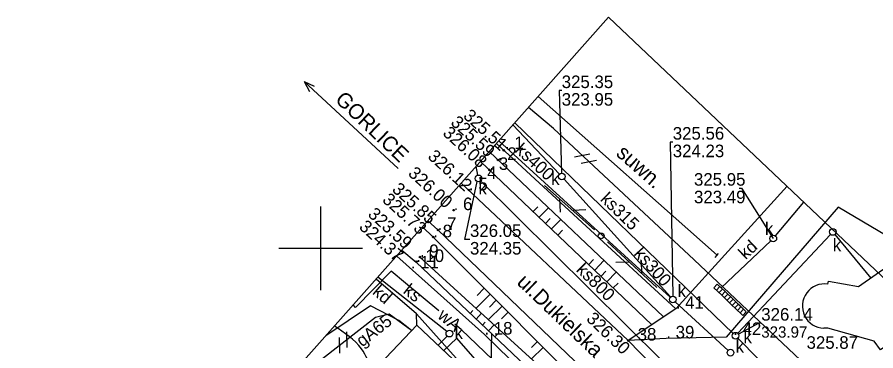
# Model space of a CAD drawing. Extents: x 4632591 to 4653165, y 5351032 to 5369868.
# Drawn here: x 4644663.8 to 4644766.2, y 5358587.8 to 5358627.6 of the extents above; entities that cross this region are included whole.
import ezdxf

# ---------------------------------------------------------------- set-up
doc = ezdxf.new("R2010")
doc.units = 0
for name, color, linetype in [('EADPD_238', 7, 'Continuous'), ('EBUPP_312', 7, 'Continuous'), ('EDZPX_299', 7, 'Continuous'), ('SDRPK_420', 7, 'Continuous'), ('SDRPK_423', 7, 'Continuous'), ('SDRPK_432', 7, 'Continuous'), ('SZOPO_902', 7, 'Continuous'), ('SZOPO_903', 7, 'Continuous'), ('UEEPA_510', 7, 'Continuous'), ('UGGPO_553', 7, 'Continuous'), ('UKKPA_506', 7, 'Continuous'), ('UKKPA_509', 7, 'Continuous'), ('UKKPB_562', 7, 'Continuous'), ('UTTTA_521', 7, 'Continuous'), ('UWWPO_581', 7, 'Continuous'), ('Warstwa 40', 7, 'Continuous'), ('Warstwa 60', 7, 'Continuous'), ('Warstwa 62', 7, 'Continuous'), ('WUKPS_403', 7, 'Continuous'), ('WUKPS_820', 7, 'Continuous'), ('WUKPS_823', 7, 'Continuous'), ('WUKPS_824', 7, 'Continuous'), ('WWRPH_811', 7, 'Continuous')]:
    doc.layers.add(name, color=color, linetype=linetype)

msp = doc.modelspace()

# ---------------------------------------------------------------- linework, layer by layer
at = {"layer": 'EBUPP_312'}
for p, q in [((4644747.26, 5358599.16), (4644725.93, 5358618.12)), ((4644747.05, 5358598.91), (4644747.43, 5358599.36)), ((4644705.01, 5358584.02), (4644711.46, 5358590.84)), ((4644711.46, 5358590.84), (4644718.85, 5358583.85)), ((4644760.46, 5358590.46), (4644759.99, 5358590.46))]:
    msp.add_line(p, q, dxfattribs=at)
for points in [[(4644760.47, 5358595.72), (4644760.54, 5358596.09), (4644764.13, 5358595.43), (4644775.98, 5358603.7), (4644780.37, 5358597.41), (4644775.58, 5358594.07)], [(4644771.51, 5358581.18), (4644771.79, 5358585.56), (4644769.05, 5358589.47), (4644766.74, 5358587.89), (4644765.98, 5358588.9), (4644760.46, 5358590.46)]]:
    msp.add_lwpolyline(points, dxfattribs=at)
msp.add_arc((4644760.08, 5358593.1), 2.65, 81.3979, 268.009, dxfattribs=at)
at = {"layer": 'EDZPX_299'}
for p, q in [((4644730.26, 5358610.92), (4644732.09, 5358611.26)), ((4644731.06, 5358610.17), (4644732.89, 5358610.51)), ((4644703.16, 5358588.16), (4644703.1, 5358590.02)), ((4644702.29, 5358587.48), (4644702.23, 5358589.34))]:
    msp.add_line(p, q, dxfattribs=at)
at = {"layer": 'SDRPK_420'}
msp.add_line((4644742.34, 5358592.78), (4644736.68, 5358588.98), dxfattribs=at)
for points in [[(4644716.77, 5358607.78), (4644736.68, 5358588.98), (4644743.87, 5358581.58), (4644750.16, 5358575.12), (4644760.49, 5358564.21), (4644766.47, 5358558.47), (4644774.19, 5358550.53), (4644786.69, 5358537.74), (4644789.51, 5358534.89)], [(4644712.76, 5358603.26), (4644713.95, 5358602.19), (4644735.11, 5358581.89), (4644746.11, 5358570.7), (4644757.33, 5358559.27), (4644771.55, 5358544.69), (4644780.39, 5358535.5), (4644785.1, 5358530.72)]]:
    msp.add_lwpolyline(points, dxfattribs=at)
at = {"layer": 'SDRPK_423'}
msp.add_line((4644741.21, 5358589.24), (4644736.68, 5358588.98), dxfattribs=at)
msp.add_lwpolyline([(4644770.35, 5358599.76), (4644761.7, 5358604.91), (4644748.36, 5358589.39), (4644741.21, 5358589.24)], dxfattribs=at)
at = {"layer": 'SDRPK_432'}
msp.add_line((4644698.03, 5358619.91), (4644698.67, 5358618.73), dxfattribs=at)
msp.add_lwpolyline([(4644709.25, 5358609.51), (4644698.03, 5358619.91), (4644699.24, 5358619.33)], dxfattribs=at)
at = {"layer": 'SZOPO_902'}
msp.add_lwpolyline([(4644720.96, 5358612.51), (4644742.34, 5358592.78), (4644755.61, 5358607.4)], dxfattribs=at)
at = {"layer": 'SZOPO_903'}
msp.add_lwpolyline([(4644709.09, 5358599.07), (4644719.52, 5358589.7), (4644731.52, 5358578)], dxfattribs=at)
at = {"layer": 'UEEPA_510'}
msp.add_circle((4644733.44, 5358601.48), 0.35, dxfattribs=at)
at = {"layer": 'UGGPO_553'}
for points in [[(4644783.41, 5358581.03), (4644773.38, 5358571.35), (4644744.52, 5358598.63), (4644727.75, 5358614.29), (4644724.77, 5358616.81)], [(4644710.84, 5358590.18), (4644709.32, 5358591.39), (4644705.94, 5358593.14), (4644700.61, 5358589.55)], [(4644710.84, 5358590.18), (4644708.18, 5358592.13), (4644706.52, 5358591.75), (4644693.55, 5358581.58)]]:
    msp.add_lwpolyline(points, dxfattribs=at)
at = {"layer": 'UKKPA_506'}
for points in [[(4644728.74, 5358618.82), (4644728.44, 5358618.82), (4644728.73, 5358608.96)], [(4644741.98, 5358612.67), (4644741.68, 5358612.67), (4644741.97, 5358594.29)], [(4644717.8, 5358601.04), (4644717.2, 5358601.06), (4644718.67, 5358607.96)], [(4644749.89, 5358607.17), (4644750.19, 5358607.17), (4644753.96, 5358601.16)], [(4644752.53, 5358591.06), (4644752.23, 5358591.06), (4644749.81, 5358589.75)]]:
    msp.add_lwpolyline(points, dxfattribs=at)
for centre in [(4644728.76, 5358608.56), (4644718.81, 5358608.34), (4644761.06, 5358601.95), (4644753.96, 5358601.16), (4644741.98, 5358593.89), (4644715.35, 5358589.81), (4644749.46, 5358589.56), (4644748.87, 5358587.54)]:
    msp.add_circle(centre, 0.4, dxfattribs=at)
at = {"layer": 'UKKPA_509'}
for p, q in [((4644747.6, 5358595.43), (4644747.18, 5358594.99)), ((4644747.49, 5358594.69), (4644747.92, 5358595.13)), ((4644748.54, 5358594.52), (4644748.12, 5358594.09)), ((4644748.44, 5358593.78), (4644748.86, 5358594.22)), ((4644749.49, 5358593.62), (4644749.06, 5358593.18)), ((4644749.38, 5358592.88), (4644749.8, 5358593.32)), ((4644750.11, 5358593.02), (4644749.69, 5358592.58)), ((4644750.01, 5358592.28), (4644750.43, 5358592.72))]:
    msp.add_line(p, q, dxfattribs=at)
for points in [[(4644747.29, 5358595.73), (4644748.23, 5358594.83), (4644747.81, 5358594.39), (4644746.87, 5358595.29)], [(4644748.23, 5358594.83), (4644749.17, 5358593.92), (4644748.75, 5358593.48), (4644747.81, 5358594.39)], [(4644749.17, 5358593.92), (4644750.11, 5358593.02), (4644749.69, 5358592.58), (4644748.75, 5358593.48)], [(4644749.8, 5358593.32), (4644750.74, 5358592.42), (4644750.32, 5358591.98), (4644749.38, 5358592.88)]]:
    msp.add_lwpolyline(points, close=True, dxfattribs=at)
at = {"layer": 'UKKPB_562'}
for p, q in [((4644728.48, 5358608.85), (4644722.93, 5358614.73)), ((4644749.17, 5358589.84), (4644723.15, 5358614.98)), ((4644741.68, 5358594.16), (4644721.25, 5358612.84)), ((4644718.74, 5358608.73), (4644718.55, 5358609.79)), ((4644741.71, 5358594.19), (4644729.03, 5358608.26)), ((4644754.22, 5358601.47), (4644757.59, 5358605.52)), ((4644747.75, 5358595.29), (4644753.67, 5358600.89)), ((4644760.79, 5358601.66), (4644749.73, 5358589.85)), ((4644761.31, 5358601.64), (4644765.59, 5358596.45)), ((4644748.58, 5358587.81), (4644742.27, 5358593.62)), ((4644711.46, 5358590.84), (4644711.44, 5358592.16))]:
    msp.add_line(p, q, dxfattribs=at)
for points in [[(4644719.07, 5358608.03), (4644749.38, 5358577.96)], [(4644718.85, 5358583.85), (4644711.44, 5358592.16), (4644706.62, 5358596.32)], [(4644715.04, 5358590.06), (4644706.81, 5358596.54)], [(4644714.01, 5358588.42), (4644715.07, 5358589.52)], [(4644749.74, 5358589.28), (4644771.59, 5358567.02)]]:
    msp.add_lwpolyline(points, dxfattribs=at)
at = {"layer": 'UTTTA_521'}
for p, q in [((4644732.66, 5358602.18), (4644726.68, 5358607.5)), ((4644728.47, 5358605.9), (4644728.57, 5358604.3)), ((4644730.02, 5358604.53), (4644731.61, 5358604.62)), ((4644734.21, 5358600.77), (4644740.06, 5358595.31)), ((4644736.79, 5358598.36), (4644735.19, 5358598.3)), ((4644738.31, 5358596.95), (4644738.25, 5358598.55))]:
    msp.add_line(p, q, dxfattribs=at)
at = {"layer": 'UWWPO_581'}
for points in [[(4644714.1, 5358592.52), (4644710.12, 5358595.82), (4644708.4, 5358597.25), (4644704.15, 5358592.94), (4644703.87, 5358593.23)], [(4644734.99, 5358571.06), (4644724.04, 5358580.83), (4644721.45, 5358585.79), (4644716.76, 5358590.31), (4644715.99, 5358590.95)], [(4644722.06, 5358580.45), (4644720.03, 5358584.88), (4644716.23, 5358589.27), (4644714.67, 5358587.81)]]:
    msp.add_lwpolyline(points, dxfattribs=at)
at = {"layer": 'Warstwa 40'}
msp.add_lwpolyline([(4644810.83, 5358555.03), (4644734.32, 5358627.59), (4644688.9, 5358576.34), (4644696.21, 5358541.05), (4644665.65, 5358513.08), (4644675.21, 5358482.87), (4644634.26, 5358446.15), (4644624.66, 5358448.08), (4644610.34, 5358444.41), (4644593.08, 5358445.77), (4644584.82, 5358446.42), (4644558.95, 5358331.35), (4644690.29, 5358293.2), (4644705.73, 5358386.52), (4644692.29, 5358404.57), (4644776.59, 5358522.67)], close=True, dxfattribs=at)
at = {"layer": 'Warstwa 60'}
for p, q in [((4644700, 5358595), (4644700, 5358605)), ((4644695, 5358600), (4644705, 5358600))]:
    msp.add_line(p, q, dxfattribs=at)
at = {"layer": 'WUKPS_403'}
for centre in [(4644721.83, 5358611.69), (4644721.14, 5358610.54), (4644720.12, 5358609.36), (4644717.7, 5358606.95), (4644715.86, 5358604.55), (4644714, 5358602.17), (4644713.43, 5358601.34), (4644711.84, 5358598.95), (4644711.39, 5358598.4), (4644736.68, 5358588.98)]:
    msp.add_circle(centre, 0.09, dxfattribs=at)
at = {"layer": 'WUKPS_820'}
for p, q in [((4644725.35, 5358604.37), (4644725.9, 5358604.94)), ((4644726.06, 5358603.7), (4644727.15, 5358604.84)), ((4644726.81, 5358602.97), (4644727.36, 5358603.55)), ((4644727.52, 5358602.3), (4644728.62, 5358603.45)), ((4644728.28, 5358601.58), (4644728.83, 5358602.15)), ((4644731.96, 5358598.06), (4644732.52, 5358598.64)), ((4644732.67, 5358597.39), (4644733.78, 5358598.55)), ((4644733.43, 5358596.66), (4644733.98, 5358597.25)), ((4644734.13, 5358595.99), (4644735.24, 5358597.16)), ((4644734.89, 5358595.27), (4644735.45, 5358595.85)), ((4644719.51, 5358595.22), (4644718.65, 5358594.37)), ((4644720.19, 5358594.53), (4644718.52, 5358592.86)), ((4644720.93, 5358593.79), (4644720.11, 5358592.97)), ((4644717.83, 5358592.22), (4644718.15, 5358592.56)), ((4644721.62, 5358593.1), (4644720.01, 5358591.49)), ((4644718.54, 5358591.55), (4644719.19, 5358592.24)), ((4644722.36, 5358592.36), (4644721.57, 5358591.57)), ((4644719.3, 5358590.83), (4644719.63, 5358591.18)), ((4644720.01, 5358590.16), (4644720.68, 5358590.87)), ((4644720.77, 5358589.44), (4644721.11, 5358589.8)), ((4644725.85, 5358588.86), (4644725.14, 5358588.16)), ((4644726.53, 5358588.17), (4644725.15, 5358586.79))]:
    msp.add_line(p, q, dxfattribs=at)
at = {"layer": 'WUKPS_823'}
msp.add_line((4644719.06, 5358610.37), (4644739.5, 5358590.87), dxfattribs=at)
for points in [[(4644712.13, 5358602.55), (4644713.43, 5358601.31), (4644734.25, 5358580.44)], [(4644709.66, 5358599.76), (4644711.37, 5358598.36), (4644732.07, 5358578.71)]]:
    msp.add_lwpolyline(points, dxfattribs=at)
at = {"layer": 'WUKPS_824'}
for p, q in [((4644720.1, 5358611.53), (4644740.89, 5358591.81)), ((4644711.84, 5358598.95), (4644732.98, 5358579.64))]:
    msp.add_line(p, q, dxfattribs=at)
at = {"layer": 'WWRPH_811'}
for points in [[(4644706.2, 5358585.27), (4644704.86, 5358588.01), (4644701.64, 5358590.71)], [(4644719.35, 5358579.58), (4644720.36, 5358583.57), (4644720.36, 5358587.15), (4644720.42, 5358589.77)]]:
    msp.add_spline(points, degree=3, dxfattribs=at)

# ---------------------------------------------------------------- texts
at = {"layer": 'EADPD_238'}
msp.add_text('suwn.', height=1.8, rotation=318.3714, dxfattribs=at).set_placement((4644735.11, 5358611.17))
at = {"layer": 'SDRPK_432'}
for s, p in [('GORLICE', (4644701.61, 5358617.62)), ('ul.Dukielska', (4644723.28, 5358595.82))]:
    msp.add_text(s, height=1.8, rotation=316.1883, dxfattribs=at).set_placement(p)
at = {"layer": 'UGGPO_553'}
msp.add_text('gA65', height=1.5, rotation=38.0978, dxfattribs=at).set_placement((4644704.96, 5358588.15))
at = {"layer": 'UKKPA_506'}
for s, height, p in [('325.35', 1.5, (4644728.74, 5358619.12)), ('323.95', 1.5, (4644728.74, 5358617.02)), ('325.56', 1.5, (4644741.98, 5358612.97)), ('324.23', 1.5, (4644741.98, 5358610.87)), ('k', 1.5, (4644727.47, 5358607.57)), ('325.95', 1.5, (4644744.51, 5358607.47)), ('k', 1.5, (4644718.81, 5358606.43)), ('323.49', 1.5, (4644744.51, 5358605.37)), ('326.05', 1.5, (4644717.8, 5358601.35)), ('k', 1.5, (4644752.97, 5358601.59)), ('324.35', 1.5, (4644717.8, 5358599.25)), ('k', 1.5, (4644761.06, 5358599.65)), ('k', 1.5, (4644742.55, 5358594.17)), ('326.14', 1.5, (4644752.53, 5358591.36)), ('k', 1.5, (4644715.97, 5358589.15)), ('323.97', 1.344, (4644752.53, 5358589.33)), ('k', 1.5, (4644750.41, 5358588.67)), ('325.87', 1.5, (4644757.93, 5358588)), ('k', 1.5, (4644749.47, 5358587.54))]:
    msp.add_text(s, height=height, dxfattribs=at).set_placement(p)
at = {"layer": 'UKKPB_562'}
for s, rotation, p in [('ks400', 317.5799, (4644723.06, 5358611.58)), ('ks315', 315.9764, (4644733.25, 5358605.75)), ('kd', 43.3947, (4644750.67, 5358598.57)), ('ks300', 312.034, (4644737.25, 5358599.29)), ('ks800', 315.2195, (4644730.38, 5358597.34)), ('kd', 319.2256, (4644706.07, 5358594.62)), ('ks', 321.7642, (4644709.73, 5358594.72))]:
    msp.add_text(s, height=1.5, rotation=rotation, dxfattribs=at).set_placement(p)
at = {"layer": 'UWWPO_581'}
msp.add_text('wA', height=1.5, rotation=320.326, dxfattribs=at).set_placement((4644713.84, 5358591.76))
at = {"layer": 'Warstwa 62'}
for s, p in [('. 1', (4644721.98, 5358611.84)), ('. 2', (4644721.13, 5358610.55)), ('. 3', (4644720.13, 5358609.35)), ('. 4', (4644718.74, 5358608.27)), ('. 5', (4644717.68, 5358606.92)), ('. 6', (4644715.86, 5358604.55)), ('. 8', (4644713.43, 5358601.31)), ('. 7', (4644713.95, 5358602.19)), ('. 10', (4644711.37, 5358598.36)), ('. 9', (4644711.84, 5358598.95)), ('. 11', (4644710.74, 5358597.59)), ('. 41', (4644742.34, 5358592.78)), ('. 18', (4644719.52, 5358589.7)), ('. 38', (4644736.68, 5358588.98)), ('. 39', (4644741.21, 5358589.24)), ('. 42', (4644749.19, 5358589.65))]:
    msp.add_text(s, height=1.5, dxfattribs=at).set_placement(p)
at = {"layer": 'WUKPS_403'}
for s, rotation, p in [('325.51', 317.5935, (4644716.9, 5358615.66)), ('325.59', 317.5935, (4644715.4, 5358614.87)), ('326.08', 317.5935, (4644714.45, 5358613.61)), ('326.12', 317.5935, (4644712.67, 5358610.82)), ('326.00', 317.5935, (4644710.33, 5358608.8)), ('325.85', 317.5935, (4644708.41, 5358606.9)), ('325.73', 317.5935, (4644707.25, 5358605.65)), ('323.59', 317.5935, (4644705.53, 5358603.92)), ('324.37', 317.5935, (4644704.48, 5358602.42)), ('326.30', 316.1883, (4644731.58, 5358591.46))]:
    msp.add_text(s, height=1.5, rotation=rotation, dxfattribs=at).set_placement(p)

doc.saveas('drawing.dxf')
